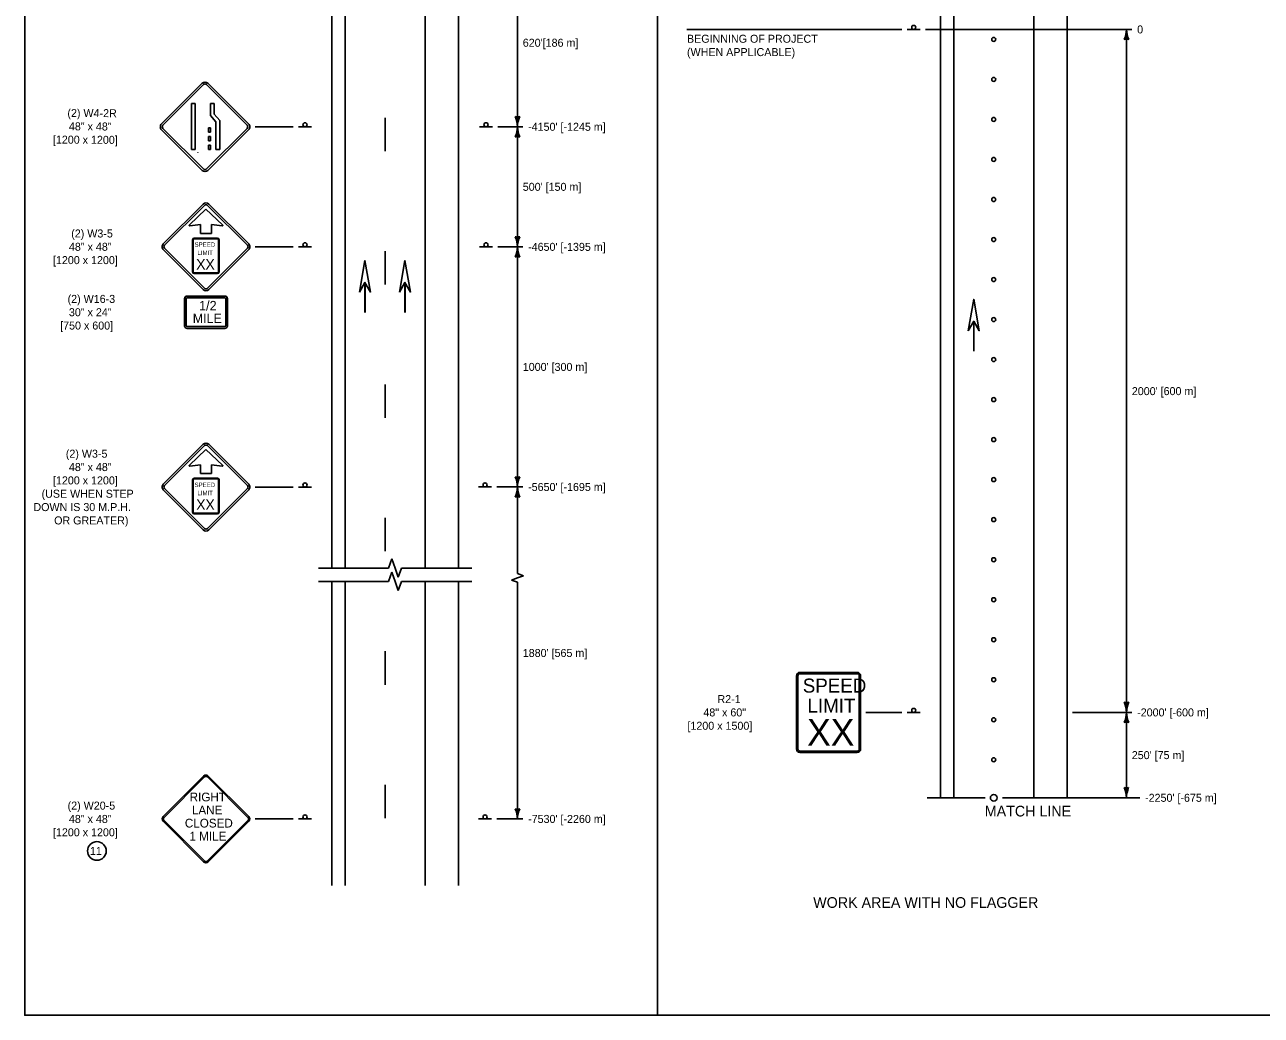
# Model space of a CAD drawing. Extents: x 49991.4 to 50021, y 49987.6 to 50011.4.
# Drawn here: x 49999.38 to 50008.66, y 49987.8 to 49995.22 of the extents above; entities that cross this region are included whole.
import ezdxf

# ---------------------------------------------------------------- set-up
doc = ezdxf.new("R2010")
doc.units = 0
for name, color, linetype in [('Level 1', 7, 'Continuous'), ('Level 2', 7, 'Continuous'), ('Level 25', 7, 'Continuous'), ('Level 3', 7, 'Continuous'), ('Level 6', 7, 'Continuous')]:
    doc.layers.add(name, color=color, linetype=linetype)

msp = doc.modelspace()

# ---------------------------------------------------------------- linework, layer by layer
at = {"layer": 'Level 1'}
for p, q in [((50001.6854, 49991.1511), (50001.6854, 49998.194)), ((50001.7854, 49991.1511), (50001.7854, 49998.194)), ((50002.3854, 49991.1511), (50002.3854, 49998.194)), ((50002.6354, 49991.1511), (50002.6354, 49998.194)), ((50006.25, 49989.429), (50006.25, 49998.194)), ((50006.35, 49989.429), (50006.35, 49998.194)), ((50006.95, 49989.4296), (50006.95, 49998.194)), ((50007.2, 49989.4294), (50007.2, 49998.194)), ((50006.002, 49995.189), (50006.098, 49995.189)), ((50002.0854, 49994.277), (50002.0854, 49994.527)), ((50001.4374, 49994.4589), (50001.5334, 49994.4589)), ((50002.7946, 49994.459), (50002.8906, 49994.459)), ((50000.7212, 49993.8801), (50000.4219, 49993.5808)), ((50000.7313, 49993.87), (50000.432, 49993.5707)), ((50000.7426, 49993.8417), (50000.6182, 49993.7244)), ((50000.7212, 49993.8801), (50000.7212, 49993.8801)), ((50000.7313, 49993.87), (50000.7313, 49993.87)), ((50000.867, 49993.7244), (50000.7426, 49993.8417)), ((50001.0532, 49993.5707), (50000.7539, 49993.87)), ((50001.0633, 49993.5808), (50000.764, 49993.8801)), ((50000.6222, 49993.7157), (50000.7023, 49993.7257)), ((50000.7023, 49993.7257), (50000.7023, 49993.6602)), ((50000.7023, 49993.6602), (50000.7829, 49993.6602)), ((50000.7829, 49993.6602), (50000.7829, 49993.7257)), ((50000.7829, 49993.7257), (50000.8629, 49993.7157)), ((50000.6422, 49993.3714), (50000.6422, 49993.6127)), ((50000.6474, 49993.3714), (50000.6474, 49993.6127)), ((50000.6547, 49993.6252), (50000.8294, 49993.6252)), ((50000.6547, 49993.62), (50000.8294, 49993.62)), ((50000.7421, 49993.6252), (50000.7421, 49993.6252)), ((50000.8367, 49993.6127), (50000.8367, 49993.3714)), ((50000.8419, 49993.6127), (50000.8419, 49993.3714)), ((50001.4374, 49993.5594), (50001.5334, 49993.5594)), ((50002.7946, 49993.559), (50002.8906, 49993.559)), ((50000.4219, 49993.5381), (50000.7212, 49993.2388)), ((50000.432, 49993.5482), (50000.7313, 49993.2489)), ((50000.7539, 49993.2489), (50001.0532, 49993.5482)), ((50000.764, 49993.2388), (50001.0633, 49993.5381)), ((50002.0854, 49993.277), (50002.0854, 49993.527)), ((50000.8294, 49993.3641), (50000.6547, 49993.3641)), ((50000.8294, 49993.3589), (50000.6547, 49993.3589)), ((50001.9351, 49993.0662), (50001.9351, 49993.2921)), ((50001.9354, 49993.0662), (50001.9354, 49993.2921)), ((50002.2351, 49993.0662), (50002.2351, 49993.2921)), ((50002.2354, 49993.0662), (50002.2354, 49993.2921)), ((50000.8837, 49993.1899), (50000.6015, 49993.1899)), ((50000.5813, 49993.1697), (50000.5813, 49992.9681)), ((50000.5947, 49992.9681), (50000.5947, 49993.1697)), ((50000.6015, 49993.1765), (50000.8837, 49993.1765)), ((50000.8904, 49993.1697), (50000.8904, 49992.9681)), ((50000.9039, 49992.9681), (50000.9039, 49993.1697)), ((50006.5, 49992.776), (50006.5, 49993.0019)), ((50006.5003, 49992.776), (50006.5003, 49993.0019)), ((50000.8837, 49992.9614), (50000.6015, 49992.9614)), ((50000.6015, 49992.948), (50000.8837, 49992.948)), ((50002.0854, 49992.277), (50002.0854, 49992.527)), ((50000.7212, 49992.079), (50000.4219, 49991.7797)), ((50000.7212, 49992.079), (50000.7212, 49992.079)), ((50001.0633, 49991.7797), (50000.764, 49992.079)), ((50000.7313, 49992.0689), (50000.432, 49991.7696)), ((50000.7426, 49992.0405), (50000.6182, 49991.9232)), ((50000.7313, 49992.0689), (50000.7313, 49992.0689)), ((50000.867, 49991.9232), (50000.7426, 49992.0405)), ((50001.0532, 49991.7696), (50000.7539, 49992.0689)), ((50000.6222, 49991.9146), (50000.7023, 49991.9246)), ((50000.7023, 49991.9246), (50000.7023, 49991.8591)), ((50000.7829, 49991.8591), (50000.7829, 49991.9246)), ((50000.7829, 49991.9246), (50000.8629, 49991.9146)), ((50000.6422, 49991.5702), (50000.6422, 49991.8115)), ((50000.6474, 49991.5702), (50000.6474, 49991.8115)), ((50000.6547, 49991.824), (50000.8294, 49991.824)), ((50000.6547, 49991.8188), (50000.8294, 49991.8188)), ((50000.7023, 49991.8591), (50000.7829, 49991.8591)), ((50000.7421, 49991.824), (50000.7421, 49991.824)), ((50000.8367, 49991.8115), (50000.8367, 49991.5702)), ((50000.8419, 49991.8115), (50000.8419, 49991.5702)), ((50000.4219, 49991.7369), (50000.7212, 49991.4376)), ((50000.432, 49991.747), (50000.7313, 49991.4477)), ((50000.7539, 49991.4477), (50001.0532, 49991.747)), ((50000.764, 49991.4376), (50001.0633, 49991.7369)), ((50001.4374, 49991.7584), (50001.5334, 49991.7584)), ((50002.7874, 49991.759), (50002.8834, 49991.759)), ((50000.8294, 49991.563), (50000.6547, 49991.563)), ((50000.8294, 49991.5578), (50000.6547, 49991.5578)), ((50002.0854, 49991.277), (50002.0854, 49991.527)), ((50001.6854, 49988.7704), (50001.6854, 49991.0511)), ((50001.7854, 49988.7704), (50001.7854, 49991.0511)), ((50002.3854, 49988.7704), (50002.3854, 49991.0511)), ((50002.6354, 49988.7704), (50002.6354, 49991.0511)), ((50002.0854, 49990.277), (50002.0854, 49990.527)), ((50005.172, 49989.794), (50005.172, 49990.344)), ((50005.182, 49989.794), (50005.182, 49990.344)), ((50005.197, 49990.369), (50005.627, 49990.369)), ((50005.197, 49990.359), (50005.627, 49990.359)), ((50005.642, 49990.344), (50005.642, 49989.794)), ((50005.652, 49990.344), (50005.652, 49989.794)), ((50006.002, 49990.069), (50006.098, 49990.069)), ((50005.627, 49989.779), (50005.197, 49989.779)), ((50005.627, 49989.769), (50005.197, 49989.769)), ((50000.4208, 49989.2881), (50000.7249, 49989.5921)), ((50000.4279, 49989.281), (50000.7319, 49989.5851)), ((50000.7532, 49989.5851), (50001.0572, 49989.281)), ((50000.7602, 49989.5921), (50001.0643, 49989.2881)), ((50002.0854, 49989.277), (50002.0854, 49989.527)), ((50000.7249, 49988.9487), (50000.4208, 49989.2527)), ((50000.7319, 49988.9557), (50000.4279, 49989.2598)), ((50001.0572, 49989.2598), (50000.7532, 49988.9557)), ((50001.0643, 49989.2527), (50000.7602, 49988.9487)), ((50001.4374, 49989.2704), (50001.5334, 49989.2704)), ((50002.7874, 49989.2705), (50002.8834, 49989.2705))]:
    msp.add_line(p, q, dxfattribs=at)
for points in [[(49999.3835, 49998.9992), (50016.7501, 49998.9992), (50016.7501, 49987.7988), (49999.3835, 49987.7988)], [(50001.8934, 49993.2198), (50001.9351, 49993.4563), (50001.977, 49993.2198), (50001.9351, 49993.292)], [(50002.1934, 49993.2198), (50002.2351, 49993.4563), (50002.277, 49993.2198), (50002.2351, 49993.292)], [(50006.4583, 49992.9296), (50006.5, 49993.1661), (50006.5419, 49992.9296), (50006.5, 49993.0018)]]:
    msp.add_lwpolyline(points, close=True, dxfattribs=at)
for centre, radius in [((50006.05, 49995.2042), 0.0152), ((50006.65, 49995.114), 0.015), ((50006.65, 49994.814), 0.015), ((50001.4854, 49994.4741), 0.0152), ((50002.8426, 49994.4742), 0.0152), ((50006.65, 49994.514), 0.015), ((50006.65, 49994.214), 0.015), ((50006.65, 49993.914), 0.015), ((50001.4854, 49993.5746), 0.0152), ((50002.8426, 49993.5742), 0.0152), ((50006.65, 49993.614), 0.015), ((50006.65, 49993.314), 0.015), ((50006.65, 49993.014), 0.015), ((50006.65, 49992.714), 0.015), ((50006.65, 49992.414), 0.015), ((50006.65, 49992.114), 0.015), ((50006.65, 49991.814), 0.015), ((50001.4854, 49991.7736), 0.0152), ((50002.8354, 49991.7742), 0.0152), ((50006.65, 49991.514), 0.015), ((50006.65, 49991.214), 0.015), ((50006.65, 49990.914), 0.015), ((50006.65, 49990.614), 0.015), ((50006.65, 49990.314), 0.015), ((50006.05, 49990.0842), 0.0152), ((50006.65, 49990.014), 0.015), ((50006.65, 49989.714), 0.015), ((50006.6501, 49989.429), 0.025), ((50001.4854, 49989.2857), 0.0152), ((50002.8354, 49989.2857), 0.0152)]:
    msp.add_circle(centre, radius, dxfattribs=at)
for centre, radius, start, end in [((50000.7426, 49993.8587), 0.0302, 45.00007, 134.99993), ((50000.7426, 49993.8587), 0.016, 45.00007, 134.99993), ((50000.6217, 49993.7208), 0.00508, 134.62874, 275.82948), ((50000.8634, 49993.7208), 0.00509, 264.38259, 45.16491), ((50000.4433, 49993.5594), 0.0302, 134.99993, 225.00008), ((50000.4433, 49993.5594), 0.016, 134.99993, 225.00008), ((50000.6547, 49993.6127), 0.0125, 90, 180), ((50000.6547, 49993.6127), 0.00728, 90, 180), ((50000.8294, 49993.6127), 0.0125, 360, 90), ((50000.8294, 49993.6127), 0.00728, 360, 90), ((50001.0419, 49993.5594), 0.016, 314.99993, 45.00007), ((50001.0419, 49993.5594), 0.0302, 314.99993, 45.00008), ((50000.6547, 49993.3714), 0.0125, 180, 270), ((50000.6547, 49993.3714), 0.00728, 180, 270), ((50000.8294, 49993.3714), 0.00728, 270, 360), ((50000.8294, 49993.3714), 0.0125, 270, 360), ((50000.6015, 49993.1697), 0.0202, 90, 180), ((50000.7426, 49993.2601), 0.0302, 225.00007, 314.99993), ((50000.7426, 49993.2601), 0.016, 225.00007, 314.99993), ((50000.8837, 49993.1697), 0.0202, 0, 90), ((50000.6015, 49993.1697), 0.00672, 90, 180), ((50000.8837, 49993.1697), 0.00672, 0, 90), ((50000.6015, 49992.9681), 0.0202, 180, 270), ((50000.6015, 49992.9681), 0.00672, 180, 270), ((50000.8837, 49992.9681), 0.00672, 270, 0), ((50000.8837, 49992.9681), 0.0202, 270, 0), ((50000.7426, 49992.0576), 0.0302, 45.00007, 134.99993), ((50000.7426, 49992.0576), 0.016, 45.00007, 134.99993), ((50000.6217, 49991.9196), 0.00508, 134.62874, 275.82948), ((50000.8634, 49991.9196), 0.00509, 264.38259, 45.16491), ((50000.6547, 49991.8115), 0.0125, 90, 180), ((50000.6547, 49991.8115), 0.00728, 90, 180), ((50000.8294, 49991.8115), 0.0125, 360, 90), ((50000.8294, 49991.8115), 0.00728, 360, 90), ((50000.4433, 49991.7583), 0.0302, 134.99993, 225.00008), ((50000.4433, 49991.7583), 0.016, 134.99993, 225.00008), ((50001.0419, 49991.7583), 0.016, 314.99993, 45.00007), ((50001.0419, 49991.7583), 0.0302, 314.99993, 45.00008), ((50000.6547, 49991.5702), 0.0125, 180, 270), ((50000.6547, 49991.5702), 0.00728, 180, 270), ((50000.8294, 49991.5702), 0.00728, 270, 360), ((50000.8294, 49991.5702), 0.0125, 270, 360), ((50000.7426, 49991.459), 0.0302, 225.00007, 314.99993), ((50000.7426, 49991.459), 0.016, 225.00007, 314.99993), ((50005.197, 49990.344), 0.025, 90, 180), ((50005.197, 49990.344), 0.015, 90, 180), ((50005.627, 49990.344), 0.025, 0, 90), ((50005.627, 49990.344), 0.015, 0, 90), ((50005.197, 49989.794), 0.025, 180, 270), ((50005.197, 49989.794), 0.015, 180, 270), ((50005.627, 49989.794), 0.025, 270, 0), ((50005.627, 49989.794), 0.015, 270, 0), ((50000.7426, 49989.5745), 0.025, 45, 135), ((50000.7426, 49989.5745), 0.015, 45, 135), ((50000.4385, 49989.2704), 0.025, 134.99976, 225), ((50000.4385, 49989.2704), 0.015, 134.99976, 225), ((50001.0466, 49989.2704), 0.015, 315, 45), ((50001.0466, 49989.2704), 0.025, 360, 45), ((50001.0466, 49989.2704), 0.025, 315, 360), ((50000.7426, 49988.9664), 0.025, 225.00043, 315), ((50000.7426, 49988.9664), 0.015, 225.00043, 315)]:
    msp.add_arc(centre, radius, start, end, dxfattribs=at)
at = {"layer": 'Level 2'}
for p, q in [((50000.7766, 49994.5436), (50000.7766, 49994.6325)), ((50000.7766, 49994.6325), (50000.8051, 49994.6325)), ((50000.8051, 49994.6325), (50000.8051, 49994.5542)), ((50000.8173, 49994.4963), (50000.7766, 49994.5436)), ((50000.8051, 49994.5542), (50000.8458, 49994.5068)), ((50000.8173, 49994.2888), (50000.8173, 49994.4963)), ((50000.8458, 49994.5068), (50000.8458, 49994.2888)), ((50000.7617, 49994.4193), (50000.7617, 49994.4519)), ((50000.7617, 49994.4519), (50000.7768, 49994.4519)), ((50000.7768, 49994.4193), (50000.7617, 49994.4193)), ((50000.7768, 49994.4519), (50000.7768, 49994.4193)), ((50000.7613, 49994.2888), (50000.7613, 49994.3214)), ((50000.7613, 49994.3214), (50000.7764, 49994.3214)), ((50000.7617, 49994.3541), (50000.7617, 49994.3866)), ((50000.7617, 49994.3866), (50000.7768, 49994.3866)), ((50000.7768, 49994.3541), (50000.7617, 49994.3541)), ((50000.7764, 49994.3214), (50000.7764, 49994.2888)), ((50000.7768, 49994.3866), (50000.7768, 49994.3541)), ((50000.7764, 49994.2888), (50000.7613, 49994.2888)), ((50000.8458, 49994.2888), (50000.8173, 49994.2888))]:
    msp.add_line(p, q, dxfattribs=at)
msp.add_circle((49999.9249, 49989.0304), 0.07, dxfattribs=at)
at = {"layer": 'Level 25'}
for p, q in [((50000.409, 49994.4806), (50000.7137, 49994.7853)), ((50000.724, 49994.7751), (50000.4192, 49994.4704)), ((50000.724, 49994.7751), (50000.724, 49994.7751)), ((50001.0517, 49994.4704), (50000.7469, 49994.7751)), ((50000.7572, 49994.7853), (50001.0619, 49994.4806)), ((50000.6617, 49994.6325), (50000.6332, 49994.6325)), ((50000.6332, 49994.6325), (50000.6332, 49994.2888)), ((50000.6617, 49994.2888), (50000.6617, 49994.6325)), ((50000.7137, 49994.1324), (50000.409, 49994.4371)), ((50000.4192, 49994.4474), (50000.724, 49994.1427)), ((50000.7469, 49994.1427), (50001.0517, 49994.4474)), ((50001.0619, 49994.4371), (50000.7572, 49994.1324)), ((50000.6332, 49994.2888), (50000.6617, 49994.2888))]:
    msp.add_line(p, q, dxfattribs=at)
msp.add_lwpolyline([(50000.6805, 49994.2673), (50000.6807, 49994.2676)], dxfattribs=at)
for centre, radius, start, end in [((50000.7355, 49994.7636), 0.0308, 45.00007, 134.99993), ((50000.7355, 49994.7636), 0.0162, 45.00007, 134.99993), ((50000.4307, 49994.4589), 0.0308, 134.99993, 225.00008), ((50000.4307, 49994.4589), 0.0162, 134.99993, 225.00008), ((50001.0402, 49994.4589), 0.0162, 314.99993, 45.00007), ((50001.0402, 49994.4589), 0.0308, 314.99993, 45.00008), ((50000.7355, 49994.1541), 0.0308, 225.00007, 314.99993), ((50000.7355, 49994.1541), 0.0162, 225.00007, 314.99993)]:
    msp.add_arc(centre, radius, start, end, dxfattribs=at)
at = {"layer": 'Level 3'}
for p, q in [((50004.1287, 49998.9992), (50004.1287, 49987.7988)), ((50003.0784, 49995.719), (50003.0784, 49994.459)), ((50005.962, 49995.189), (50004.3498, 49995.189)), ((50007.6857, 49995.189), (50006.138, 49995.189)), ((50007.6457, 49995.189), (50007.6457, 49991.959)), ((50001.3974, 49994.4589), (50001.111, 49994.4589)), ((50003.1184, 49994.459), (50002.9306, 49994.459)), ((50003.0784, 49994.459), (50003.0784, 49993.559)), ((50001.3974, 49993.5594), (50001.1121, 49993.5594)), ((50003.1184, 49993.559), (50002.9306, 49993.559)), ((50003.0784, 49993.559), (50003.0784, 49991.759)), ((50007.6457, 49991.959), (50007.6457, 49990.069)), ((50001.3974, 49991.7584), (50001.1121, 49991.7584)), ((50003.1184, 49991.759), (50002.9234, 49991.759)), ((50003.0784, 49991.7591), (50003.0783, 49991.1102)), ((50003.0783, 49991.0778), (50003.0326, 49991.0616)), ((50003.0783, 49991.0454), (50003.0326, 49991.0616)), ((50003.124, 49991.094), (50003.0783, 49991.1102)), ((50003.124, 49991.094), (50003.0783, 49991.0778)), ((50003.0784, 49991.0454), (50003.0784, 49989.2705)), ((50005.962, 49990.069), (50005.692, 49990.069)), ((50007.6858, 49990.069), (50007.24, 49990.069)), ((50007.645, 49989.429), (50007.6457, 49990.069)), ((50001.3974, 49989.2704), (50001.1117, 49989.2704)), ((50002.9234, 49989.2705), (50003.1184, 49989.2705))]:
    msp.add_line(p, q, dxfattribs=at)
for centre, radius, start, end in [((50007.413, 49995.2005), 0.233, 337.92284, 357.17269), ((50007.8679, 49995.1982), 0.2223, 182.36048, 202.54399), ((50007.6457, 49995.0608), 0.0548, 72.13882, 107.86118), ((50003.0784, 49994.5872), 0.0548, 252.13882, 287.86118), ((50002.8457, 49994.4475), 0.233, 2.82731, 22.07716), ((50003.3005, 49994.4498), 0.2223, 157.45601, 177.63952), ((50002.8562, 49994.4682), 0.2223, 337.45601, 357.63952), ((50003.3111, 49994.4705), 0.233, 182.82731, 202.07716), ((50003.0784, 49994.3308), 0.0548, 72.13882, 107.86118), ((50003.0784, 49993.6872), 0.0548, 252.13882, 287.86118), ((50002.8457, 49993.5475), 0.233, 2.82731, 22.07716), ((50002.8562, 49993.5682), 0.2223, 337.45601, 357.63952), ((50003.3005, 49993.5498), 0.2223, 157.45601, 177.63952), ((50003.3111, 49993.5705), 0.233, 182.82731, 202.07716), ((50003.0784, 49993.4308), 0.0548, 72.13882, 107.86118), ((50003.0784, 49991.8872), 0.0548, 252.13882, 287.86118), ((50002.8457, 49991.7475), 0.233, 2.82731, 22.07716), ((50003.3005, 49991.7498), 0.2223, 157.45601, 177.63952), ((50002.8562, 49991.7682), 0.2223, 337.45601, 357.63952), ((50003.3111, 49991.7705), 0.233, 182.82731, 202.07716), ((50003.0784, 49991.6308), 0.0548, 72.13882, 107.86118), ((50007.6457, 49990.1972), 0.0548, 252.13882, 287.86118), ((50007.413, 49990.0575), 0.233, 2.82731, 22.07716), ((50007.8679, 49990.0598), 0.2223, 157.45601, 177.63952), ((50007.4236, 49990.0782), 0.2223, 337.45601, 357.63952), ((50007.8784, 49990.0805), 0.233, 182.82731, 202.07716), ((50007.6457, 49989.9408), 0.0548, 72.13882, 107.86118), ((50007.645, 49989.5572), 0.0548, 252.13882, 287.86118), ((50007.4123, 49989.4175), 0.233, 2.82731, 22.07716), ((50007.8671, 49989.4198), 0.2223, 157.45601, 177.63952), ((50003.0784, 49989.3987), 0.0548, 252.13882, 287.86118), ((50002.8457, 49989.259), 0.233, 2.82731, 22.07716), ((50003.3005, 49989.2613), 0.2223, 157.45601, 177.63952)]:
    msp.add_arc(centre, radius, start, end, dxfattribs=at)
at = {"layer": 'Level 6'}
for p, q in [((50001.5854, 49991.1511), (50002.1118, 49991.1511)), ((50002.1361, 49991.2197), (50002.1118, 49991.1511)), ((50002.1361, 49991.2197), (50002.1604, 49991.1511)), ((50002.1604, 49991.1511), (50002.1847, 49991.0825)), ((50002.209, 49991.1511), (50002.1847, 49991.0825)), ((50002.209, 49991.1511), (50002.7354, 49991.1511)), ((50002.1361, 49991.1197), (50002.1118, 49991.0511)), ((50002.1361, 49991.1197), (50002.1604, 49991.0511)), ((50001.5854, 49991.0511), (50002.1118, 49991.0511)), ((50002.1604, 49991.0511), (50002.1847, 49990.9825)), ((50002.209, 49991.0511), (50002.1847, 49990.9825)), ((50002.209, 49991.0511), (50002.7354, 49991.0511)), ((50006.1501, 49989.429), (50006.5851, 49989.429)), ((50006.7151, 49989.4297), (50007.745, 49989.429))]:
    msp.add_line(p, q, dxfattribs=at)

# ---------------------------------------------------------------- texts
at = {"layer": 'Level 1'}
for s, height, p in [('SPEED', 0.03301, (50000.6567, 49993.5595)), ('XX', 0.07775, (50000.6696, 49993.389)), ('LIMIT', 0.03301, (50000.6786, 49993.4985)), ('SPEED', 0.03301, (50000.6567, 49991.7583)), ('LIMIT', 0.03301, (50000.6786, 49991.6973)), ('XX', 0.07775, (50000.6696, 49991.5879))]:
    msp.add_text(s, height=height, rotation=360, dxfattribs=at).set_placement(p)
for s, height, p in [('1/2', 0.07124, (50000.6902, 49993.0824)), ('MILE', 0.06989, (50000.6439, 49992.9883)), ('SPEED', 0.10512, (50005.2182, 49990.2174)), ('LIMIT', 0.10512, (50005.2536, 49990.0673)), ('XX', 0.19892, (50005.2505, 49989.82)), ('RIGHT', 0.06543, (50000.6202, 49989.4022)), ('LANE', 0.06543, (50000.6372, 49989.3042)), ('CLOSED', 0.06543, (50000.5842, 49989.2063)), ('1 MILE', 0.06543, (50000.6183, 49989.1084))]:
    msp.add_text(s, height=height, dxfattribs=at).set_placement(p)
at = {"layer": 'Level 2'}
for s, height, p in [('BEGINNING OF PROJECT', 0.06, (50004.3498, 49995.089)), ('0', 0.06, (50007.7257, 49995.159)), ("620'[186 m]", 0.06, (50003.1184, 49995.059)), ('(WHEN APPLICABLE)', 0.06, (50004.3498, 49994.989)), ("-4150' [-1245 m]", 0.06, (50003.1584, 49994.429)), ("500' [150 m]", 0.06, (50003.1184, 49993.979)), ('(2) W3-5', 0.06, (49999.7321, 49993.6293)), ('48" x 48"', 0.06, (49999.7148, 49993.5294)), ("-4650' [-1395 m]", 0.06, (50003.1584, 49993.529)), ('[1200 x 1200]', 0.06, (49999.5954, 49993.4295)), ('(2) W16-3', 0.06, (49999.7049, 49993.1388)), ('30" x 24"', 0.06, (49999.7148, 49993.0389)), ('[750 x 600]', 0.06, (49999.6492, 49992.939)), ("1000' [300 m]", 0.06, (50003.1184, 49992.629)), ("2000' [600 m]", 0.06, (50007.6857, 49992.4475)), ('(2) W3-5', 0.06, (49999.6916, 49991.9783)), ('48" x 48"', 0.06, (49999.7148, 49991.8783)), ('[1200 x 1200]', 0.06, (49999.5954, 49991.7783)), ('(USE WHEN STEP', 0.06, (49999.5099, 49991.6783)), ("-5650' [-1695 m]", 0.06, (50003.1584, 49991.729)), ('DOWN IS 30 M.P.H.', 0.06, (49999.4487, 49991.5783)), ('OR GREATER)', 0.06, (49999.6041, 49991.4783)), ("1880' [565 m]", 0.06, (50003.1184, 49990.4847)), ('R2-1', 0.06, (50004.5783, 49990.139)), ('48" x 60"', 0.06, (50004.4727, 49990.039)), ("-2000' [-600 m]", 0.06, (50007.7258, 49990.039)), ('[1200 x 1500]', 0.06, (50004.3533, 49989.939)), ("250' [75 m]", 0.06, (50007.6854, 49989.719)), ('(2) W20-5', 0.06, (49999.7052, 49989.3404)), ("-2250' [-675 m]", 0.06, (50007.785, 49989.399)), ('48" x 48"', 0.06, (49999.7148, 49989.2404)), ("-7530' [-2260 m] ", 0.06, (50003.1584, 49989.2405)), ('MATCH LINE', 0.08, (50006.583, 49989.289)), ('[1200 x 1200]', 0.06, (49999.5954, 49989.1404)), ('11', 0.06, (49999.8722, 49989.0004)), ('WORK AREA WITH NO FLAGGER', 0.08, (50005.2965, 49988.604))]:
    msp.add_text(s, height=height, dxfattribs=at).set_placement(p)
for s, p in [('(2) W4-2R', (49999.7035, 49994.5324)), ('48" x 48"', (49999.7147, 49994.4324)), ('[1200 x 1200]', (49999.5948, 49994.3329))]:
    msp.add_text(s, height=0.06, rotation=359.76569, dxfattribs=at).set_placement(p)

doc.saveas('drawing.dxf')
